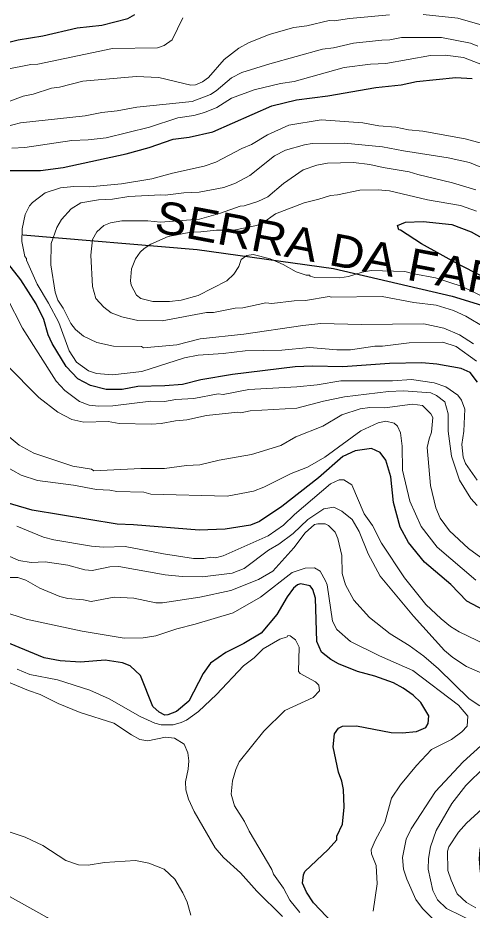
# Model space of a CAD drawing. Extents: x 598.3 to 623.2, y 6902.2 to 6930.1.
# Drawn here: x 609.437 to 610.559, y 6912.154 to 6914.358 of the extents above; entities that cross this region are included whole.
import ezdxf
from ezdxf.enums import TextEntityAlignment as Align

# ---------------------------------------------------------------- set-up
doc = ezdxf.new("R2010")
doc.units = 0
doc.header["$LTSCALE"] = 0.032
for name, color, linetype, lineweight in [('1', 7, 'Continuous', 25), ('2', 7, 'Continuous', 13), ('26', 7, 'Continuous', 25)]:
    doc.layers.add(name, color=color, linetype=linetype, lineweight=lineweight)

msp = doc.modelspace()

# ---------------------------------------------------------------- linework, layer by layer
at = {"layer": '1'}
for points in [[(609.3954, 6914.2932), (609.4379, 6914.3038), (609.499, 6914.3143), (609.5836, 6914.3338), (609.6447, 6914.3402), (609.7089, 6914.3569), (609.7261, 6914.3669)], [(609.3737, 6913.9815), (609.493, 6913.9809), (609.5489, 6913.9887), (609.7043, 6914.0227), (609.7613, 6914.0377), (609.8209, 6914.0584), (609.8597, 6914.0632), (609.9183, 6914.0771), (610.064, 6914.1412), (610.1249, 6914.1555), (610.2023, 6914.1659), (610.3214, 6914.1864), (610.3834, 6914.1931), (610.4213, 6914.201), (610.5184, 6914.2113), (610.5589, 6914.2086)], [(610.6311, 6913.6954), (610.5259, 6913.7487), (610.4342, 6913.8003), (610.3823, 6913.8338), (610.3779, 6913.8344), (610.3748, 6913.8452), (610.3941, 6913.8536), (610.438, 6913.8552), (610.5086, 6913.8475), (610.5566, 6913.8298), (610.6031, 6913.8033)], [(610.5724, 6913.4581), (610.5542, 6913.482), (610.5316, 6913.4919), (610.4714, 6913.5031), (610.4343, 6913.5063), (610.3544, 6913.5047), (610.2393, 6913.4967), (610.1648, 6913.4983), (610.1217, 6913.4966), (609.9669, 6913.4772), (609.8892, 6913.4643), (609.844, 6913.4529), (609.8002, 6913.4491), (609.7332, 6913.448), (609.6943, 6913.4407), (609.6554, 6913.44), (609.6167, 6913.4498), (609.5848, 6913.4665), (609.5566, 6913.4973), (609.5221, 6913.5536), (609.5122, 6913.575), (609.501, 6913.6135), (609.4819, 6913.6518), (609.4444, 6913.7116), (609.4115, 6913.753)], [(610.5454, 6912.9176), (610.5059, 6912.9589), (610.4412, 6913.0139), (610.4013, 6913.062), (610.3808, 6913.1006), (610.3648, 6913.1615), (610.3584, 6913.2246), (610.3461, 6913.2654), (610.3314, 6913.2847), (610.31, 6913.2949), (610.2696, 6913.2886), (610.2399, 6913.2751), (610.1797, 6913.2223), (610.0885, 6913.1509), (610.0337, 6913.1141), (610.0117, 6913.1048), (609.9491, 6913.0952), (609.8848, 6913.0927), (609.7224, 6913.1064), (609.6825, 6913.1078), (609.4725, 6913.1421), (609.3899, 6913.1664)], [(610.2287, 6912.4951), (610.216, 6912.5573), (610.219, 6912.5895), (610.2287, 6912.6035), (610.2386, 6912.6086), (610.2729, 6912.6094), (610.3587, 6912.5932), (610.3859, 6912.5926), (610.4212, 6912.5956), (610.4444, 6912.6056), (610.4506, 6912.6151), (610.4523, 6912.6343), (610.4322, 6912.6675), (610.4129, 6912.6852), (610.3889, 6912.7027), (610.3649, 6912.7158), (610.3186, 6912.7322), (610.2761, 6912.7436), (610.2292, 6912.7623), (610.21, 6912.7731), (610.1868, 6912.7916), (610.1753, 6912.8182), (610.1722, 6912.9251), (610.1657, 6912.9461), (610.1586, 6912.9556), (610.1349, 6912.9599), (610.1277, 6912.9575), (610.118, 6912.9494), (610.1018, 6912.9284), (610.0769, 6912.8849), (610.0378, 6912.8385), (609.9948, 6912.8128), (609.9506, 6912.7907), (609.9126, 6912.7642), (609.8946, 6912.7385), (609.8589, 6912.6702), (609.8287, 6912.6449), (609.8071, 6912.6364), (609.7998, 6912.6362), (609.7856, 6912.6433), (609.77, 6912.6572), (609.7399, 6912.734), (609.714, 6912.7575), (609.6955, 6912.765), (609.6528, 6912.7713), (609.5919, 6912.7665), (609.5415, 6912.77), (609.5022, 6912.7777), (609.4162, 6912.813)], [(610.7812, 6912.152), (610.7523, 6912.1675), (610.6404, 6912.1925), (610.6105, 6912.205), (610.586, 6912.2336), (610.5793, 6912.2486), (610.5769, 6912.2808), (610.5785, 6912.3031), (610.5881, 6912.3469), (610.6087, 6912.3879), (610.6259, 6912.4091), (610.6854, 6912.4653), (610.7685, 6912.5315), (610.7981, 6912.5651), (610.8278, 6912.6108), (610.8693, 6912.6971), (610.8941, 6912.803), (610.8911, 6912.8244), (610.8862, 6912.8368), (610.8761, 6912.847), (610.8465, 6912.8651), (610.709, 6912.8617), (610.6021, 6912.8882), (610.5454, 6912.9176)], [(610.2307, 6912.1057), (610.1669, 6912.1725), (610.1497, 6912.1983), (610.1399, 6912.2209), (610.1422, 6912.2416), (610.146, 6912.2497), (610.2035, 6912.304), (610.2244, 6912.3281), (610.225, 6912.3369), (610.2387, 6912.3668), (610.2426, 6912.4088), (610.2411, 6912.4521), (610.237, 6912.4731), (610.2287, 6912.4951)]]:
    msp.add_lwpolyline(points, dxfattribs=at)
at = {"layer": '2'}
for points in [[(609.3243, 6914.1176), (609.4501, 6914.1652), (609.4747, 6914.1701), (609.5201, 6914.1847), (609.5395, 6914.1872), (609.5975, 6914.2016), (609.729, 6914.2131), (609.7851, 6914.2114), (609.8646, 6914.1924), (609.8756, 6914.1927), (609.8932, 6914.2006), (609.9079, 6914.2111), (609.9465, 6914.2553), (609.9826, 6914.2833), (610.0062, 6914.2963), (610.0574, 6914.317), (610.1186, 6914.3344), (610.1503, 6914.339), (610.2057, 6914.3522), (610.2183, 6914.3507), (610.2562, 6914.357), (610.3546, 6914.3659)], [(609.8442, 6914.3585), (609.8185, 6914.3038)], [(610.4382, 6914.3669), (610.5238, 6914.3578), (610.5777, 6914.3421), (610.6023, 6914.3306), (610.6625, 6914.2876)], [(609.386, 6914.0844), (609.444, 6914.0989), (609.6029, 6914.1159), (609.6447, 6914.1248), (609.6822, 6914.1289), (609.7308, 6914.1378), (609.8676, 6914.1514), (609.9124, 6914.1689), (609.9265, 6914.1778), (609.965, 6914.2105), (609.9904, 6914.2233), (610.0596, 6914.2451), (610.1891, 6914.2808), (610.2166, 6914.284), (610.2659, 6914.2955), (610.3355, 6914.3036), (610.3557, 6914.3037), (610.3846, 6914.3094), (610.4833, 6914.3101), (610.5546, 6914.2955), (610.5732, 6914.2885)], [(609.8185, 6914.3038), (609.7984, 6914.2901), (609.7823, 6914.2843), (609.6709, 6914.2827), (609.4864, 6914.2438), (609.4694, 6914.2429), (609.4067, 6914.2309)], [(609.4224, 6914.0365), (609.4541, 6914.038), (609.5702, 6914.0552), (609.611, 6914.0568), (609.6548, 6914.0623), (609.7622, 6914.088), (609.832, 6914.111), (609.8718, 6914.1172), (609.898, 6914.1243), (609.9282, 6914.1372), (609.965, 6914.1603), (610.0207, 6914.1804), (610.0859, 6914.1959), (610.1195, 6914.2014), (610.2432, 6914.2356), (610.3077, 6914.2437), (610.3454, 6914.2453), (610.4561, 6914.2657), (610.4922, 6914.2665), (610.5379, 6914.26), (610.6354, 6914.2226)], [(610.5845, 6914.048), (610.5419, 6914.0591), (610.4374, 6914.0787), (610.402, 6914.082), (610.3703, 6914.0883), (610.3287, 6914.0916), (610.2891, 6914.0988), (610.186, 6914.1061), (610.1058, 6914.0932), (610.0538, 6914.0696), (610.0141, 6914.0457), (609.9899, 6914.0352), (609.9259, 6914.0016), (609.8973, 6913.9921), (609.8187, 6913.9749), (609.7682, 6913.961), (609.6927, 6913.9482), (609.6141, 6913.9412), (609.5753, 6913.9418), (609.5424, 6913.9385), (609.5045, 6913.9261), (609.4731, 6913.9024), (609.4657, 6913.8941), (609.4549, 6913.8723), (609.4476, 6913.8373), (609.4471, 6913.8057), (609.4546, 6913.7685), (609.4582, 6913.7643), (609.4583, 6913.76), (609.4844, 6913.7001), (609.5131, 6913.6539), (609.5382, 6913.6054), (609.5635, 6913.5355), (609.5822, 6913.5079)], [(610.5624, 6913.5532), (610.5279, 6913.575), (610.4893, 6913.5922), (610.4393, 6913.6026), (610.2846, 6913.6011), (610.185, 6913.6034), (610.1404, 6913.5987), (609.9947, 6913.5768), (609.8873, 6913.5654), (609.8296, 6913.551), (609.7475, 6913.5436), (609.7421, 6913.5468), (609.6731, 6913.5477), (609.6317, 6913.5561), (609.5988, 6913.5722), (609.5798, 6913.5884), (609.5677, 6913.6032), (609.5488, 6913.641), (609.5357, 6913.6607), (609.5292, 6913.6805), (609.5181, 6913.7482), (609.5197, 6913.8008), (609.533, 6913.8404), (609.5446, 6913.8601), (609.5683, 6913.8867), (609.5928, 6913.9013), (609.6363, 6913.9086), (609.671, 6913.9101), (609.7108, 6913.9167), (609.7899, 6913.9215), (609.8007, 6913.92), (609.8471, 6913.9265), (609.8847, 6913.9279), (609.9458, 6913.9395), (609.9745, 6913.9498), (610.0098, 6913.969), (610.0711, 6914.0171), (610.0983, 6914.0315), (610.1445, 6914.0446), (610.1639, 6914.0478), (610.244, 6914.0486), (610.3376, 6914.0397), (610.389, 6914.0297), (610.4998, 6914.0129), (610.5525, 6914.001), (610.6185, 6913.9737)], [(610.5902, 6913.5936), (610.5432, 6913.6211), (610.5129, 6913.6354), (610.4704, 6913.6488), (610.4151, 6913.6549), (610.3363, 6913.6698), (610.2111, 6913.6683), (610.2056, 6913.6699), (610.147, 6913.66), (610.1191, 6913.6594), (610.0646, 6913.6529), (610.0495, 6913.6545), (609.9928, 6913.6424), (609.9737, 6913.6416), (609.9202, 6913.6302), (609.9032, 6913.6301), (609.7937, 6913.61), (609.7333, 6913.6108), (609.6937, 6913.62), (609.6676, 6913.6299), (609.649, 6913.6435), (609.6294, 6913.6653), (609.621, 6913.6948), (609.617, 6913.7725), (609.6217, 6913.8105), (609.6319, 6913.8296), (609.6497, 6913.845), (609.6658, 6913.852), (609.6941, 6913.8568), (609.7583, 6913.8568), (609.7897, 6913.8535), (609.8859, 6913.8609), (609.9377, 6913.8755), (609.986, 6913.8932), (609.996, 6913.8941), (610.03, 6913.9046), (610.0542, 6913.9161), (610.093, 6913.9493), (610.142, 6913.983), (610.1752, 6913.9944), (610.2016, 6913.9994), (610.2655, 6914.001), (610.3064, 6913.9961), (610.3395, 6913.9884), (610.4035, 6913.9783), (610.4246, 6913.9713), (610.5104, 6913.9508), (610.5679, 6913.9333)], [(610.0603, 6913.763), (610.0184, 6913.7734), (610.0025, 6913.7711), (609.9886, 6913.7614), (609.9827, 6913.7444), (609.97, 6913.7252), (609.9533, 6913.7091), (609.8819, 6913.6721), (609.8401, 6913.6609), (609.8118, 6913.6578), (609.7702, 6913.6578), (609.7404, 6913.6652), (609.7304, 6913.673), (609.717, 6913.6982), (609.7149, 6913.7087), (609.7173, 6913.7381), (609.7272, 6913.7627), (609.7387, 6913.7795), (609.7488, 6913.7888), (609.7657, 6913.7992), (609.8079, 6913.8179), (609.8644, 6913.8293), (609.8892, 6913.8294), (609.9275, 6913.8341), (609.9701, 6913.8342), (610.026, 6913.8454), (610.0411, 6913.8512), (610.0735, 6913.8746), (610.1439, 6913.9018), (610.1806, 6913.9103), (610.2094, 6913.9199), (610.2262, 6913.9208), (610.2818, 6913.9329), (610.327, 6913.9338), (610.3549, 6913.9314), (610.4488, 6913.9087), (610.5298, 6913.8949), (610.5694, 6913.8809)], [(610.2534, 6913.7193), (610.2322, 6913.7161), (610.1704, 6913.7168), (610.1587, 6913.7201), (610.1573, 6913.7224), (610.1487, 6913.7226), (610.1242, 6913.731), (610.0924, 6913.749), (610.0603, 6913.763)], [(610.6015, 6913.6616), (610.5346, 6913.6947), (610.4683, 6913.716), (610.4148, 6913.7257), (610.3924, 6913.7321), (610.3095, 6913.7345), (610.2869, 6913.7305), (610.2534, 6913.7193)], [(610.5714, 6913.2163), (610.5427, 6913.2575), (610.5364, 6913.2735), (610.5333, 6913.3047), (610.5381, 6913.3374), (610.5404, 6913.392), (610.5323, 6913.4141), (610.5234, 6913.4264), (610.4939, 6913.4471), (610.465, 6913.457), (610.4092, 6913.4649), (610.3622, 6913.4619), (610.2348, 6913.4618), (610.176, 6913.4521), (610.126, 6913.4471), (610.0071, 6913.4407), (609.9442, 6913.4279), (609.9318, 6913.4294), (609.8714, 6913.4181), (609.8272, 6913.4158), (609.7991, 6913.4108), (609.7656, 6913.4116), (609.6712, 6913.4003), (609.6372, 6913.3995), (609.6132, 6913.402), (609.5892, 6913.4109), (609.5529, 6913.4375), (609.5315, 6913.4607), (609.4487, 6913.5919), (609.4101, 6913.6677)], [(610.1573, 6913.5444), (610.2247, 6913.5379), (610.2583, 6913.5379), (610.3182, 6913.5477), (610.3376, 6913.5477), (610.4037, 6913.5557), (610.4863, 6913.5573), (610.519, 6913.5466), (610.5696, 6913.5102)], [(609.5822, 6913.5079), (609.6115, 6913.486), (609.6309, 6913.4796), (609.6709, 6913.4764), (609.7435, 6913.4845), (609.8485, 6913.5184), (609.8827, 6913.525), (609.9441, 6913.5294), (609.9984, 6913.5362), (610.089, 6913.5371), (610.1573, 6913.5444)], [(610.5711, 6913.1536), (610.5554, 6913.1713), (610.5276, 6913.2163), (610.5079, 6913.2758), (610.4996, 6913.3374), (610.5, 6913.38), (610.4911, 6913.4098), (610.4707, 6913.4255), (610.4568, 6913.4319), (610.3897, 6913.4367), (610.3519, 6913.435), (610.2434, 6913.4221), (610.1914, 6913.4116), (610.126, 6913.3945), (610.0106, 6913.3874), (609.9873, 6913.3825), (609.9806, 6913.3839), (609.9032, 6913.376), (609.854, 6913.3652), (609.826, 6913.3631), (609.7907, 6913.3566), (609.7667, 6913.355), (609.6876, 6913.3566), (609.6602, 6913.3615), (609.5998, 6913.3599), (609.5707, 6913.3658), (609.5356, 6913.3845), (609.4888, 6913.4203), (609.4084, 6913.5019)], [(610.6253, 6912.9925), (610.5499, 6913.0478), (610.5033, 6913.091), (610.4802, 6913.1221), (610.4691, 6913.1478), (610.4564, 6913.2034), (610.4482, 6913.297), (610.4524, 6913.3188), (610.4588, 6913.3353), (610.462, 6913.3708), (610.4568, 6913.3804), (610.4362, 6913.401), (610.4113, 6913.4043), (610.3434, 6913.395), (610.3064, 6913.3962), (610.2821, 6913.3929), (610.237, 6913.3776), (610.1903, 6913.3501), (610.1236, 6913.3233), (610.0862, 6913.3023), (610.0138, 6913.2797), (609.934, 6913.2659), (609.8862, 6913.2546), (609.8531, 6913.2529), (609.7991, 6913.2449), (609.7411, 6913.2448), (609.625, 6913.2392), (609.6193, 6913.2432), (609.5726, 6913.2511), (609.4769, 6913.2832), (609.4403, 6913.303), (609.3956, 6913.3399)], [(609.4041, 6913.2516), (609.4456, 6913.2285), (609.4856, 6913.2154), (609.5743, 6913.2036), (609.631, 6913.1931), (609.6641, 6913.1914), (609.6811, 6913.1882), (609.7483, 6913.1865), (609.7658, 6913.1818), (609.9542, 6913.1769), (610.0187, 6913.189), (610.0446, 6913.1988), (610.1123, 6913.2327), (610.1523, 6913.2487), (610.1952, 6913.2728), (610.2837, 6913.3378), (610.3266, 6913.3583), (610.3454, 6913.3622), (610.3663, 6913.3573), (610.3744, 6913.3494), (610.3818, 6913.3331), (610.3859, 6913.3007), (610.3868, 6913.2409), (610.405, 6913.1642), (610.4327, 6913.1019), (610.4724, 6913.0508), (610.5677, 6912.9692)], [(610.6158, 6912.7988), (610.5271, 6912.8416), (610.5055, 6912.8548), (610.4822, 6912.8736), (610.4444, 6912.9096), (610.3919, 6912.9748), (610.3351, 6913.0611), (610.3124, 6913.1046), (610.2926, 6913.133), (610.262, 6913.205), (610.2418, 6913.2173), (610.2305, 6913.2173), (610.2094, 6913.2076), (610.1204, 6913.1315), (610.0931, 6913.105), (610.0555, 6913.0789), (609.9437, 6913.0295), (609.9248, 6913.0247), (609.9132, 6913.0264), (609.896, 6913.0231), (609.871, 6913.0232), (609.7964, 6913.0344), (609.7017, 6913.0522), (609.6484, 6913.0506), (609.6188, 6913.053), (609.5263, 6913.0691), (609.5006, 6913.0756), (609.4345, 6913.1029)], [(609.3833, 6913.0427), (609.4398, 6913.0175), (609.4703, 6913.0126), (609.5042, 6913.0149), (609.5605, 6913.006), (609.6026, 6912.9947), (609.6208, 6912.9932), (609.6644, 6913.0019), (609.6865, 6913.0028), (609.8005, 6912.9827), (609.8431, 6912.9787), (609.8926, 6912.9779), (609.9664, 6912.9866), (609.9955, 6912.9978), (610.0563, 6913.0434), (610.0816, 6913.0584), (610.1168, 6913.0849), (610.1534, 6913.1191), (610.193, 6913.1454), (610.2171, 6913.1494), (610.237, 6913.1396), (610.2627, 6913.1194), (610.2796, 6913.0892), (610.3021, 6913.0343), (610.332, 6912.9796), (610.4142, 6912.8806), (610.4908, 6912.7952), (610.5111, 6912.7779), (610.5449, 6912.7558), (610.6035, 6912.7304)], [(610.5781, 6912.659), (610.5518, 6912.6766), (610.4754, 6912.7506), (610.4396, 6912.7817), (610.4036, 6912.8076), (610.3568, 6912.8371), (610.3054, 6912.8769), (610.2663, 6912.92), (610.2458, 6912.9578), (610.2378, 6912.9861), (610.2369, 6913.0306), (610.2274, 6913.0719), (610.2207, 6913.0878), (610.2045, 6913.1047), (610.196, 6913.1087), (610.178, 6913.1088), (610.1696, 6913.1065), (610.1465, 6913.0864), (610.1189, 6913.0491), (610.0667, 6912.9913)], [(610.0667, 6912.9913), (610.0316, 6912.9713), (609.9629, 6912.9436), (609.8864, 6912.9273), (609.7943, 6912.913), (609.7775, 6912.9137), (609.7235, 6912.9252), (609.6752, 6912.9275), (609.6178, 6912.9163), (609.5991, 6912.921), (609.5602, 6912.9244), (609.5406, 6912.9292), (609.4914, 6912.9497), (609.4564, 6912.9697), (609.4372, 6912.9761), (609.3816, 6912.9762)], [(610.3148, 6912.1519), (610.3243, 6912.219), (610.3219, 6912.2646), (610.3107, 6912.2935), (610.3099, 6912.3034), (610.3194, 6912.3259), (610.3436, 6912.3708), (610.3598, 6912.4307), (610.3818, 6912.4637), (610.4215, 6912.5113), (610.4588, 6912.5511), (610.5082, 6912.5759), (610.5336, 6912.5945), (610.5463, 6912.6084), (610.5486, 6912.6334), (610.525, 6912.6604), (610.4121, 6912.7461), (610.3304, 6912.7821), (610.2584, 6912.818), (610.2247, 6912.8477), (610.2138, 6912.8678), (610.2005, 6912.9575), (610.1971, 6912.9678), (610.1835, 6912.9914), (610.1697, 6912.9994), (610.1463, 6912.9991), (610.1142, 6912.9883), (610.036, 6912.9274), (609.9688, 6912.8889), (609.8746, 6912.8604), (609.8293, 6912.8491), (609.7778, 6912.8322), (609.7461, 6912.8271), (609.6994, 6912.8257), (609.5961, 6912.8433), (609.4576, 6912.873), (609.4002, 6912.8918)], [(610.1333, 6912.148), (610.109, 6912.1787), (610.0927, 6912.2082), (610.0687, 6912.2433), (610.0644, 6912.2543), (610.0084, 6912.3492), (609.997, 6912.3736), (609.9721, 6912.4122), (609.9642, 6912.4408), (609.9667, 6912.4737), (609.9751, 6912.5019), (609.9835, 6912.5202), (610.0444, 6912.5964), (610.0967, 6912.6475), (610.1662, 6912.6798), (610.1819, 6912.6963), (610.1803, 6912.7103), (610.1722, 6912.7186), (610.1338, 6912.7386), (610.1302, 6912.7441), (610.1319, 6912.8038), (610.1229, 6912.8221), (610.1095, 6912.8317), (610.1037, 6912.8327), (610.1024, 6912.8296), (610.084, 6912.8235), (610.0428, 6912.7995), (610.0202, 6912.7771), (609.9946, 6912.758), (609.9277, 6912.6871), (609.8831, 6912.6448), (609.8531, 6912.6238), (609.8401, 6912.6175), (609.8205, 6912.6122), (609.7912, 6912.6119), (609.7751, 6912.616), (609.739, 6912.6325), (609.6625, 6912.6765), (609.6146, 6912.6973), (609.5346, 6912.7235), (609.4669, 6912.7364), (609.4356, 6912.7493)], [(610.0902, 6912.1386), (610.0275, 6912.2012), (609.9872, 6912.2464), (609.9447, 6912.2841), (609.924, 6912.3084), (609.8726, 6912.3976), (609.8588, 6912.4284), (609.8515, 6912.4517), (609.8509, 6912.4708), (609.8573, 6912.5023), (609.8589, 6912.5234), (609.8565, 6912.543), (609.8476, 6912.5646), (609.8241, 6912.5794), (609.8018, 6912.5819), (609.758, 6912.5722), (609.7386, 6912.5761), (609.7173, 6912.5869), (609.6739, 6912.6157), (609.5913, 6912.6425), (609.5365, 6912.665), (609.4925, 6912.687), (609.4634, 6912.6967), (609.3677, 6912.7359)], [(610.4745, 6912.1208), (610.4363, 6912.1583), (610.4197, 6912.1809), (610.3972, 6912.2308), (610.3897, 6912.2558), (610.3868, 6912.2843), (610.3959, 6912.3299), (610.4085, 6912.3552), (610.4686, 6912.447), (610.5364, 6912.5203), (610.6063, 6912.5843)], [(610.5902, 6912.5079), (610.5436, 6912.4618), (610.5086, 6912.4179), (610.4704, 6912.351), (610.4561, 6912.3106), (610.4509, 6912.2817), (610.4499, 6912.2556), (610.4617, 6912.2024), (610.473, 6912.1793), (610.4958, 6912.1579), (610.57, 6912.1223)], [(610.5683, 6912.1596), (610.5448, 6912.1732), (610.5219, 6912.1944), (610.5068, 6912.2283), (610.4992, 6912.2519), (610.4976, 6912.2996), (610.501, 6912.3107), (610.5255, 6912.347), (610.5446, 6912.369), (610.5832, 6912.4044)], [(609.4105, 6912.3494), (609.4553, 6912.3348), (609.499, 6912.3138), (609.5557, 6912.2766), (609.5867, 6912.2663), (609.611, 6912.2654), (609.6507, 6912.2718), (609.7273, 6912.2767), (609.7608, 6912.2703), (609.7986, 6912.2553), (609.8243, 6912.2304), (609.8448, 6912.1972), (609.855, 6912.1737), (609.8646, 6912.1418)], [(609.4107, 6912.1916), (609.5094, 6912.1357), (609.5346, 6912.1187), (609.595, 6912.0893), (609.7143, 6912.0605), (609.7707, 6912.0371), (609.7995, 6912.014), (609.8277, 6911.9866), (609.8551, 6911.9519), (609.8761, 6911.903), (609.886, 6911.8573), (609.9031, 6911.8247), (609.9201, 6911.806), (609.9645, 6911.772), (609.9872, 6911.7603), (610.0029, 6911.7631), (610.0135, 6911.7726), (610.0176, 6911.7884)]]:
    msp.add_lwpolyline(points, dxfattribs=at)
at = {"layer": '26'}
msp.add_lwpolyline([(609.4492, 6913.8226), (609.8798, 6913.7864), (610.2163, 6913.7394), (610.5094, 6913.6706), (610.5926, 6913.6453), (610.7157, 6913.5802), (611.0775, 6913.3739)], dxfattribs=at)

# ---------------------------------------------------------------- texts
at = {"layer": '26', "width": 1.1}
msp.add_text('SERRA DA FAROFA', height=0.08, rotation=349.276, dxfattribs=at).set_placement((610.3174, 6913.7266), align=Align.CENTER)

doc.saveas('drawing.dxf')
